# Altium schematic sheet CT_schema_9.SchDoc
size 297 x 239 mm
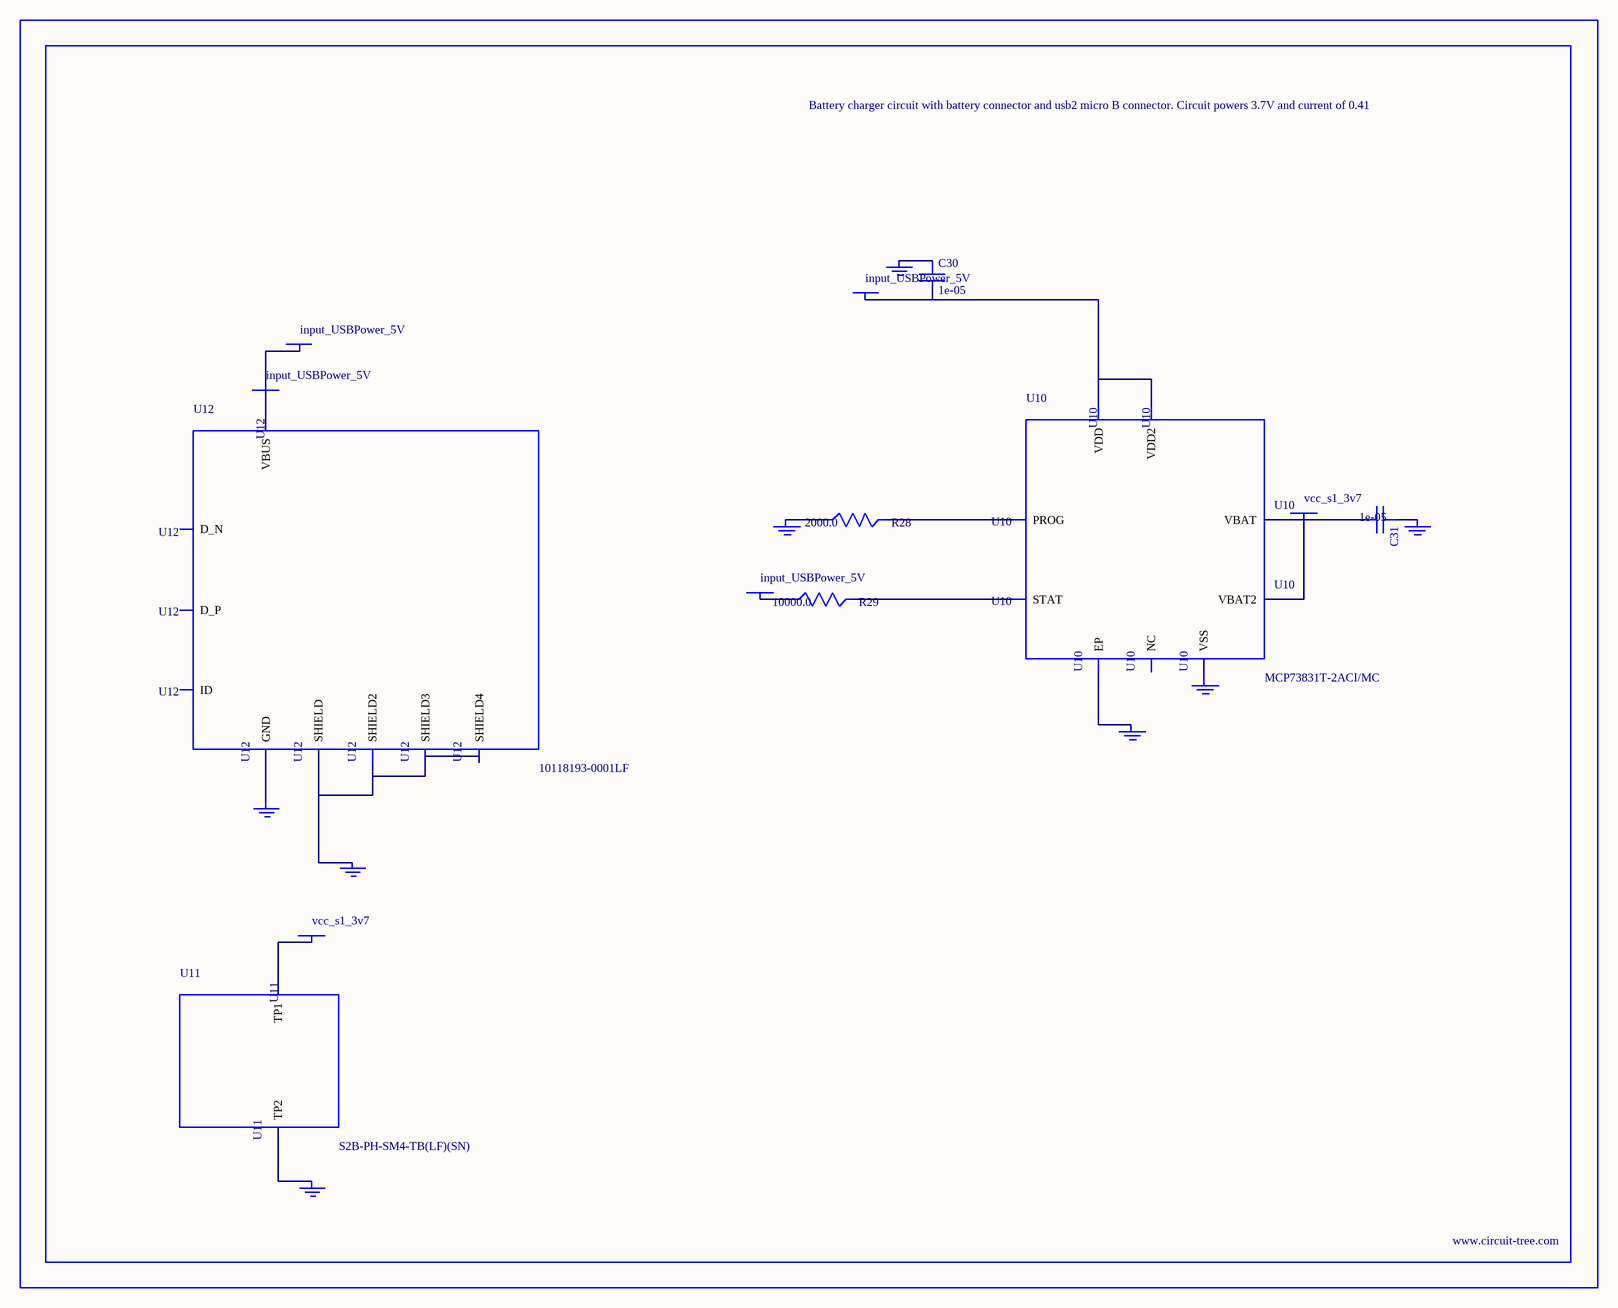
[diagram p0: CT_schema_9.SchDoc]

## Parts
BORDER8  (no value)
C30  1e-05  [C1206]
C31  1e-05  [C1206]
GND_INSTANCE_8_0  (no value)
GND_INSTANCE_8_1  (no value)
GND_INSTANCE_8_2  (no value)
GND_INSTANCE_8_3  (no value)
GND_INSTANCE_8_4  (no value)
GND_INSTANCE_8_5  (no value)
GND_INSTANCE_8_6  (no value)
GND_INSTANCE_8_7  (no value)
POWER_INSTANCE_8_0  input_USBPower_5V
POWER_INSTANCE_8_1  input_USBPower_5V
POWER_INSTANCE_8_2  vcc_s1_3v7
POWER_INSTANCE_8_3  vcc_s1_3v7
POWER_INSTANCE_8_4  input_USBPower_5V
POWER_INSTANCE_8_5  input_USBPower_5V
R28  2000.0  [R0603]
R29  10000.0  [R0603]
U10  MCP73831T-2ACI/MC  [DFN8_2X3MC]
U11  S2B-PH-SM4-TB(LF)(SN)  [JST-2-SMD]
U12  10118193-0001LF  [FCI_10118193-0001LF]

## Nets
NetC30_1: C30.1 GND_INSTANCE_8_0.0(GND)
NetC30_2: C30.2 POWER_INSTANCE_8_0.0(PWR) U10.1(VDD) U10.2(VDD2)
NetC31_1: C31.1 GND_INSTANCE_8_1.0(GND)
NetC31_2: C31.2 POWER_INSTANCE_8_2.0(PWR) U10.3(VBAT) U10.4(VBAT2)
NetGND_INSTANCE_8_2_0: GND_INSTANCE_8_2.0(GND) R28.1
NetGND_INSTANCE_8_3_0: GND_INSTANCE_8_3.0(GND) U10.9(EP)
NetGND_INSTANCE_8_4_0: GND_INSTANCE_8_4.0(GND) U10.6(VSS)
NetGND_INSTANCE_8_5_0: GND_INSTANCE_8_5.0(GND) U11.2(TP2)
NetGND_INSTANCE_8_6_0: GND_INSTANCE_8_6.0(GND) U12.6(SHIELD) U12.7(SHIELD2) U12.8(SHIELD3) U12.9(SHIELD4)
NetGND_INSTANCE_8_7_0: GND_INSTANCE_8_7.0(GND) U12.5(GND)
NetPOWER_INSTANCE_8_1_0: POWER_INSTANCE_8_1.0(PWR) R29.1
NetPOWER_INSTANCE_8_3_0: POWER_INSTANCE_8_3.0(PWR) U11.1(TP1)
NetPOWER_INSTANCE_8_4_0: POWER_INSTANCE_8_4.0(PWR) POWER_INSTANCE_8_5.0(PWR) U12.1(VBUS)
NetR28_2: R28.2 U10.8(PROG)
NetR29_2: R29.2 U10.5(STAT)

Not connected (* = marked no-connect by the designer): U10 7(NC); U12 2(D_N) 3(D_P) 4(ID)

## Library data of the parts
BORDER8 = BORDER_PAGE8
C30 C31 = C1206C106K3RACTU
GND_INSTANCE_8_0-GND_INSTANCE_8_7 = GND
POWER_INSTANCE_8_0-POWER_INSTANCE_8_5 = PWR
R28 = RC0603JR-072KL
R29 = RC0603JR-0710KL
